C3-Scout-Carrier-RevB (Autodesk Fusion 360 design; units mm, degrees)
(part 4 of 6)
sketch "Molded package profile" plane through (0, 0, 0.2) normal (0, 0, 1) x axis (1, 0, 0)
  line L1 (1.95, -2.45) -> (-1.95, -2.45)
  line L2 (1.95, 2.45) -> (1.95, -2.45)
  line L3 (-1.95, 2.45) -> (1.95, 2.45)
  line L4 (-1.95, -2.45) -> (-1.95, 2.45)
extrude "Extrude1" new body sketch "Molded package profile" along normal blind 1.1
sketch "Lead solder feet profiles" plane through (0, 0, 0) normal (0, 0, 1) x axis (1, 0, 0)
  line L1 (-2.7, 1.665) -> (-3.55, 1.665)
  line L2 (-2.7, 2.145) -> (-2.7, 1.665)
  line L3 (-3.55, 2.145) -> (-2.7, 2.145)
  line L4 (-3.55, 1.665) -> (-3.55, 2.145)
  line L5 (3.55, 1.665) -> (2.7, 1.665)
  line L6 (3.55, 2.145) -> (3.55, 1.665)
  line L7 (2.7, 2.145) -> (3.55, 2.145)
  line L8 (2.7, 1.665) -> (2.7, 2.145)
  line L9 (-2.7, 0.395) -> (-3.55, 0.395)
  line L10 (-2.7, 0.875) -> (-2.7, 0.395)
  line L11 (-3.55, 0.875) -> (-2.7, 0.875)
  line L12 (-3.55, 0.395) -> (-3.55, 0.875)
  line L13 (3.55, 0.395) -> (2.7, 0.395)
  line L14 (3.55, 0.875) -> (3.55, 0.395)
  line L15 (2.7, 0.875) -> (3.55, 0.875)
  line L16 (2.7, 0.395) -> (2.7, 0.875)
  line L17 (-2.7, -0.875) -> (-3.55, -0.875)
  line L18 (-2.7, -0.395) -> (-2.7, -0.875)
  line L19 (-3.55, -0.395) -> (-2.7, -0.395)
  line L20 (-3.55, -0.875) -> (-3.55, -0.395)
  line L21 (3.55, -0.875) -> (2.7, -0.875)
  line L22 (3.55, -0.395) -> (3.55, -0.875)
  line L23 (2.7, -0.395) -> (3.55, -0.395)
  line L24 (2.7, -0.875) -> (2.7, -0.395)
  line L25 (-2.7, -2.145) -> (-3.55, -2.145)
  line L26 (-2.7, -1.665) -> (-2.7, -2.145)
  line L27 (-3.55, -1.665) -> (-2.7, -1.665)
  line L28 (-3.55, -2.145) -> (-3.55, -1.665)
  line L29 (3.55, -2.145) -> (2.7, -2.145)
  line L30 (3.55, -1.665) -> (3.55, -2.145)
  line L31 (2.7, -1.665) -> (3.55, -1.665)
  line L32 (2.7, -2.145) -> (2.7, -1.665)
extrude "Extrude2" new body sketch "Lead solder feet profiles" along normal blind 0.15
work_plane "WorkPlane2" AlongDistance 0.1 ExtraOffset 0
sketch "Formed lead risers profiles" plane through (0, 0, 0.1) normal (0, 0, 1) x axis (1, 0, 0)
  line L1 (-2.12, 1.665) -> (-2.78, 1.665)
  line L2 (-2.12, 2.145) -> (-2.12, 1.665)
  line L3 (-2.78, 2.145) -> (-2.12, 2.145)
  line L4 (-2.78, 1.665) -> (-2.78, 2.145)
  line L5 (2.78, 1.665) -> (2.12, 1.665)
  line L6 (2.78, 2.145) -> (2.78, 1.665)
  line L7 (2.12, 2.145) -> (2.78, 2.145)
  line L8 (2.12, 1.665) -> (2.12, 2.145)
  line L9 (-2.12, 0.395) -> (-2.78, 0.395)
  line L10 (-2.12, 0.875) -> (-2.12, 0.395)
  line L11 (-2.78, 0.875) -> (-2.12, 0.875)
  line L12 (-2.78, 0.395) -> (-2.78, 0.875)
  line L13 (2.78, 0.395) -> (2.12, 0.395)
  line L14 (2.78, 0.875) -> (2.78, 0.395)
  line L15 (2.12, 0.875) -> (2.78, 0.875)
  line L16 (2.12, 0.395) -> (2.12, 0.875)
  line L17 (-2.12, -0.875) -> (-2.78, -0.875)
  line L18 (-2.12, -0.395) -> (-2.12, -0.875)
  line L19 (-2.78, -0.395) -> (-2.12, -0.395)
  line L20 (-2.78, -0.875) -> (-2.78, -0.395)
  line L21 (2.78, -0.875) -> (2.12, -0.875)
  line L22 (2.78, -0.395) -> (2.78, -0.875)
  line L23 (2.12, -0.395) -> (2.78, -0.395)
  line L24 (2.12, -0.875) -> (2.12, -0.395)
  line L25 (-2.12, -2.145) -> (-2.78, -2.145)
  line L26 (-2.12, -1.665) -> (-2.12, -2.145)
  line L27 (-2.78, -1.665) -> (-2.12, -1.665)
  line L28 (-2.78, -2.145) -> (-2.78, -1.665)
  line L29 (2.78, -2.145) -> (2.12, -2.145)
  line L30 (2.78, -1.665) -> (2.78, -2.145)
  line L31 (2.12, -1.665) -> (2.78, -1.665)
  line L32 (2.12, -2.145) -> (2.12, -1.665)
extrude "Extrude3" new body sketch "Formed lead risers profiles" along normal blind 0.45
work_plane "WorkPlane3" AlongDistance 0.45 ExtraOffset 0
sketch "Lead shoulders profiles" plane through (0, 0, 0.45) normal (0, 0, 1) x axis (1, 0, 0)
  line L1 (-1.95, 1.665) -> (-2.2, 1.665)
  line L2 (-1.95, 2.145) -> (-1.95, 1.665)
  line L3 (-2.2, 2.145) -> (-1.95, 2.145)
  line L4 (-2.2, 1.665) -> (-2.2, 2.145)
  line L5 (2.2, 1.665) -> (1.95, 1.665)
  line L6 (2.2, 2.145) -> (2.2, 1.665)
  line L7 (1.95, 2.145) -> (2.2, 2.145)
  line L8 (1.95, 1.665) -> (1.95, 2.145)
  line L9 (-1.95, 0.395) -> (-2.2, 0.395)
  line L10 (-1.95, 0.875) -> (-1.95, 0.395)
  line L11 (-2.2, 0.875) -> (-1.95, 0.875)
  line L12 (-2.2, 0.395) -> (-2.2, 0.875)
  line L13 (2.2, 0.395) -> (1.95, 0.395)
  line L14 (2.2, 0.875) -> (2.2, 0.395)
  line L15 (1.95, 0.875) -> (2.2, 0.875)
  line L16 (1.95, 0.395) -> (1.95, 0.875)
  line L17 (-1.95, -0.875) -> (-2.2, -0.875)
  line L18 (-1.95, -0.395) -> (-1.95, -0.875)
  line L19 (-2.2, -0.395) -> (-1.95, -0.395)
  line L20 (-2.2, -0.875) -> (-2.2, -0.395)
  line L21 (2.2, -0.875) -> (1.95, -0.875)
  line L22 (2.2, -0.395) -> (2.2, -0.875)
  line L23 (1.95, -0.395) -> (2.2, -0.395)
  line L24 (1.95, -0.875) -> (1.95, -0.395)
  line L25 (-1.95, -2.145) -> (-2.2, -2.145)
  line L26 (-1.95, -1.665) -> (-1.95, -2.145)
  line L27 (-2.2, -1.665) -> (-1.95, -1.665)
  line L28 (-2.2, -2.145) -> (-2.2, -1.665)
  line L29 (2.2, -2.145) -> (1.95, -2.145)
  line L30 (2.2, -1.665) -> (2.2, -2.145)
  line L31 (1.95, -1.665) -> (2.2, -1.665)
  line L32 (1.95, -2.145) -> (1.95, -1.665)
extrude "Extrude4" new body sketch "Lead shoulders profiles" along normal blind 0.15
work_plane "WorkPlane4" AlongDistance 1.3 ExtraOffset 0
sketch "Pin 1 indicator profile" plane through (0, 0, 1.3) normal (0, 0, 1) x axis (1, 0, 0)
  circle C1 centre (-1.4, 1.9) radius 0.18
extrude "Extrude5" new body sketch "Pin 1 indicator profile" along normal blind 0.015
work_plane "WorkPlane5" AlongDistance 1.3 ExtraOffset 0
sketch "4056 marking" plane through (0, 0, 1.3) normal (0, 0, 1) x axis (1, 0, 0)
  dimension "d962" = 0.7
  dimension "d963" = "'4056'"
extrude "Extrude6" new body sketch "4056 marking" along normal blind 0.012
work_plane "WorkPlane1" AlongDistance 0.2 ExtraOffset 0
sketch "Molded package profile" plane through (0, 0, 0.2) normal (0, 0, 1) x axis (1, 0, 0)
  line L1 (0.8, -1.45) -> (-0.8, -1.45)
  line L2 (0.8, 1.45) -> (0.8, -1.45)
  line L3 (-0.8, 1.45) -> (0.8, 1.45)
  line L4 (-0.8, -1.45) -> (-0.8, 1.45)
extrude "Extrude1" new body sketch "Molded package profile" along normal blind 0.9
sketch "Lead solder feet profiles" plane through (0, 0, 0) normal (0, 0, 1) x axis (1, 0, 0)
  line L1 (-1.15, 0.71) -> (-1.675, 0.71)
  line L2 (-1.15, 1.19) -> (-1.15, 0.71)
  line L3 (-1.675, 1.19) -> (-1.15, 1.19)
  line L4 (-1.675, 0.71) -> (-1.675, 1.19)
  line L5 (1.675, 0.71) -> (1.15, 0.71)
  line L6 (1.675, 1.19) -> (1.675, 0.71)
  line L7 (1.15, 1.19) -> (1.675, 1.19)
  line L8 (1.15, 0.71) -> (1.15, 1.19)
  line L9 (-1.15, -0.24) -> (-1.675, -0.24)
  line L10 (-1.15, 0.24) -> (-1.15, -0.24)
  line L11 (-1.675, 0.24) -> (-1.15, 0.24)
  line L12 (-1.675, -0.24) -> (-1.675, 0.24)
  line L13 (1.675, -0.24) -> (1.15, -0.24)
  line L14 (1.675, 0.24) -> (1.675, -0.24)
  line L15 (1.15, 0.24) -> (1.675, 0.24)
  line L16 (1.15, -0.24) -> (1.15, 0.24)
  line L17 (-1.15, -1.19) -> (-1.675, -1.19)
  line L18 (-1.15, -0.71) -> (-1.15, -1.19)
  line L19 (-1.675, -0.71) -> (-1.15, -0.71)
  line L20 (-1.675, -1.19) -> (-1.675, -0.71)
  line L21 (1.675, -1.19) -> (1.15, -1.19)
  line L22 (1.675, -0.71) -> (1.675, -1.19)
  line L23 (1.15, -0.71) -> (1.675, -0.71)
  line L24 (1.15, -1.19) -> (1.15, -0.71)
extrude "Extrude2" new body sketch "Lead solder feet profiles" along normal blind 0.15
work_plane "WorkPlane2" AlongDistance 0.1 ExtraOffset 0
sketch "Formed lead risers profiles" plane through (0, 0, 0.1) normal (0, 0, 1) x axis (1, 0, 0)
  line L1 (-0.97, 0.71) -> (-1.23, 0.71)
  line L2 (-0.97, 1.19) -> (-0.97, 0.71)
  line L3 (-1.23, 1.19) -> (-0.97, 1.19)
  line L4 (-1.23, 0.71) -> (-1.23, 1.19)
  line L5 (1.23, 0.71) -> (0.97, 0.71)
  line L6 (1.23, 1.19) -> (1.23, 0.71)
  line L7 (0.97, 1.19) -> (1.23, 1.19)
  line L8 (0.97, 0.71) -> (0.97, 1.19)
  line L9 (-0.97, -0.24) -> (-1.23, -0.24)
  line L10 (-0.97, 0.24) -> (-0.97, -0.24)
  line L11 (-1.23, 0.24) -> (-0.97, 0.24)
  line L12 (-1.23, -0.24) -> (-1.23, 0.24)
  line L13 (1.23, -0.24) -> (0.97, -0.24)
  line L14 (1.23, 0.24) -> (1.23, -0.24)
  line L15 (0.97, 0.24) -> (1.23, 0.24)
  line L16 (0.97, -0.24) -> (0.97, 0.24)
  line L17 (-0.97, -1.19) -> (-1.23, -1.19)
  line L18 (-0.97, -0.71) -> (-0.97, -1.19)
  line L19 (-1.23, -0.71) -> (-0.97, -0.71)
  line L20 (-1.23, -1.19) -> (-1.23, -0.71)
  line L21 (1.23, -1.19) -> (0.97, -1.19)
  line L22 (1.23, -0.71) -> (1.23, -1.19)
  line L23 (0.97, -0.71) -> (1.23, -0.71)
  line L24 (0.97, -1.19) -> (0.97, -0.71)
extrude "Extrude3" new body sketch "Formed lead risers profiles" along normal blind 0.45
work_plane "WorkPlane3" AlongDistance 0.45 ExtraOffset 0
sketch "Lead shoulders profiles" plane through (0, 0, 0.45) normal (0, 0, 1) x axis (1, 0, 0)
  line L1 (-0.8, 0.71) -> (-1.05, 0.71)
  line L2 (-0.8, 1.19) -> (-0.8, 0.71)
  line L3 (-1.05, 1.19) -> (-0.8, 1.19)
  line L4 (-1.05, 0.71) -> (-1.05, 1.19)
  line L5 (1.05, 0.71) -> (0.8, 0.71)
  line L6 (1.05, 1.19) -> (1.05, 0.71)
  line L7 (0.8, 1.19) -> (1.05, 1.19)
  line L8 (0.8, 0.71) -> (0.8, 1.19)
  line L9 (-0.8, -0.24) -> (-1.05, -0.24)
  line L10 (-0.8, 0.24) -> (-0.8, -0.24)
  line L11 (-1.05, 0.24) -> (-0.8, 0.24)
  line L12 (-1.05, -0.24) -> (-1.05, 0.24)
  line L13 (1.05, -0.24) -> (0.8, -0.24)
  line L14 (1.05, 0.24) -> (1.05, -0.24)
  line L15 (0.8, 0.24) -> (1.05, 0.24)
  line L16 (0.8, -0.24) -> (0.8, 0.24)
  line L17 (-0.8, -1.19) -> (-1.05, -1.19)
  line L18 (-0.8, -0.71) -> (-0.8, -1.19)
  line L19 (-1.05, -0.71) -> (-0.8, -0.71)
  line L20 (-1.05, -1.19) -> (-1.05, -0.71)
  line L21 (1.05, -1.19) -> (0.8, -1.19)
  line L22 (1.05, -0.71) -> (1.05, -1.19)
  line L23 (0.8, -0.71) -> (1.05, -0.71)
  line L24 (0.8, -1.19) -> (0.8, -0.71)
extrude "Extrude4" new body sketch "Lead shoulders profiles" along normal blind 0.15
work_plane "WorkPlane4" AlongDistance 1.1 ExtraOffset 0
sketch "Pin 1 indicator profile" plane through (0, 0, 1.1) normal (0, 0, 1) x axis (1, 0, 0)
  circle C1 centre (-0.25, 0.9) radius 0.18
extrude "Extrude5" new body sketch "Pin 1 indicator profile" along normal blind 0.015
work_plane "WorkPlane1" AlongDistance 0.2 ExtraOffset 0
sketch "Molded package profile" plane through (0, 0, 0.2) normal (0, 0, 1) x axis (1, 0, 0)
  line L1 (2.2, -1.465) -> (-2.2, -1.465)
  line L2 (2.2, 1.465) -> (2.2, -1.465)
  line L3 (-2.2, 1.465) -> (2.2, 1.465)
  line L4 (-2.2, -1.465) -> (-2.2, 1.465)
extrude "Extrude1" new body sketch "Molded package profile" along normal blind 0.9
sketch "Lead solder feet profiles" plane through (0, 0, 0) normal (0, 0, 1) x axis (1, 0, 0)
  line L1 (-2.9, 0.815) -> (-3.65, 0.815)
  line L2 (-2.9, 1.135) -> (-2.9, 0.815)
  line L3 (-3.65, 1.135) -> (-2.9, 1.135)
  line L4 (-3.65, 0.815) -> (-3.65, 1.135)
  line L5 (3.65, 0.815) -> (2.9, 0.815)
  line L6 (3.65, 1.135) -> (3.65, 0.815)
  line L7 (2.9, 1.135) -> (3.65, 1.135)
  line L8 (2.9, 0.815) -> (2.9, 1.135)
  line L9 (-2.9, 0.165) -> (-3.65, 0.165)
  line L10 (-2.9, 0.485) -> (-2.9, 0.165)
  line L11 (-3.65, 0.485) -> (-2.9, 0.485)
  line L12 (-3.65, 0.165) -> (-3.65, 0.485)
  line L13 (3.65, 0.165) -> (2.9, 0.165)
  line L14 (3.65, 0.485) -> (3.65, 0.165)
  line L15 (2.9, 0.485) -> (3.65, 0.485)
  line L16 (2.9, 0.165) -> (2.9, 0.485)
  line L17 (-2.9, -0.485) -> (-3.65, -0.485)
  line L18 (-2.9, -0.165) -> (-2.9, -0.485)
  line L19 (-3.65, -0.165) -> (-2.9, -0.165)
  line L20 (-3.65, -0.485) -> (-3.65, -0.165)
  line L21 (3.65, -0.485) -> (2.9, -0.485)
  line L22 (3.65, -0.165) -> (3.65, -0.485)
  line L23 (2.9, -0.165) -> (3.65, -0.165)
  line L24 (2.9, -0.485) -> (2.9, -0.165)
  line L25 (-2.9, -1.135) -> (-3.65, -1.135)
  line L26 (-2.9, -0.815) -> (-2.9, -1.135)
  line L27 (-3.65, -0.815) -> (-2.9, -0.815)
  line L28 (-3.65, -1.135) -> (-3.65, -0.815)
  line L29 (3.65, -1.135) -> (2.9, -1.135)
  line L30 (3.65, -0.815) -> (3.65, -1.135)
  line L31 (2.9, -0.815) -> (3.65, -0.815)
  line L32 (2.9, -1.135) -> (2.9, -0.815)
extrude "Extrude2" new body sketch "Lead solder feet profiles" along normal blind 0.15
work_plane "WorkPlane2" AlongDistance 0.1 ExtraOffset 0
sketch "Formed lead risers profiles" plane through (0, 0, 0.1) normal (0, 0, 1) x axis (1, 0, 0)
  line L1 (-2.37, 0.815) -> (-2.98, 0.815)
  line L2 (-2.37, 1.135) -> (-2.37, 0.815)
  line L3 (-2.98, 1.135) -> (-2.37, 1.135)
  line L4 (-2.98, 0.815) -> (-2.98, 1.135)
  line L5 (2.98, 0.815) -> (2.37, 0.815)
  line L6 (2.98, 1.135) -> (2.98, 0.815)
  line L7 (2.37, 1.135) -> (2.98, 1.135)
  line L8 (2.37, 0.815) -> (2.37, 1.135)
  line L9 (-2.37, 0.165) -> (-2.98, 0.165)
  line L10 (-2.37, 0.485) -> (-2.37, 0.165)
  line L11 (-2.98, 0.485) -> (-2.37, 0.485)
  line L12 (-2.98, 0.165) -> (-2.98, 0.485)
  line L13 (2.98, 0.165) -> (2.37, 0.165)
  line L14 (2.98, 0.485) -> (2.98, 0.165)
  line L15 (2.37, 0.485) -> (2.98, 0.485)
  line L16 (2.37, 0.165) -> (2.37, 0.485)
  line L17 (-2.37, -0.485) -> (-2.98, -0.485)
  line L18 (-2.37, -0.165) -> (-2.37, -0.485)
  line L19 (-2.98, -0.165) -> (-2.37, -0.165)
  line L20 (-2.98, -0.485) -> (-2.98, -0.165)
  line L21 (2.98, -0.485) -> (2.37, -0.485)
  line L22 (2.98, -0.165) -> (2.98, -0.485)
  line L23 (2.37, -0.165) -> (2.98, -0.165)
  line L24 (2.37, -0.485) -> (2.37, -0.165)
  line L25 (-2.37, -1.135) -> (-2.98, -1.135)
  line L26 (-2.37, -0.815) -> (-2.37, -1.135)
  line L27 (-2.98, -0.815) -> (-2.37, -0.815)
  line L28 (-2.98, -1.135) -> (-2.98, -0.815)
  line L29 (2.98, -1.135) -> (2.37, -1.135)
  line L30 (2.98, -0.815) -> (2.98, -1.135)
  line L31 (2.37, -0.815) -> (2.98, -0.815)
  line L32 (2.37, -1.135) -> (2.37, -0.815)
extrude "Extrude3" new body sketch "Formed lead risers profiles" along normal blind 0.45
work_plane "WorkPlane3" AlongDistance 0.45 ExtraOffset 0
sketch "Lead shoulders profiles" plane through (0, 0, 0.45) normal (0, 0, 1) x axis (1, 0, 0)
  line L1 (-2.2, 0.815) -> (-2.45, 0.815)
  line L2 (-2.2, 1.135) -> (-2.2, 0.815)
  line L3 (-2.45, 1.135) -> (-2.2, 1.135)
  line L4 (-2.45, 0.815) -> (-2.45, 1.135)
  line L5 (2.45, 0.815) -> (2.2, 0.815)
  line L6 (2.45, 1.135) -> (2.45, 0.815)
  line L7 (2.2, 1.135) -> (2.45, 1.135)
  line L8 (2.2, 0.815) -> (2.2, 1.135)
  line L9 (-2.2, 0.165) -> (-2.45, 0.165)
  line L10 (-2.2, 0.485) -> (-2.2, 0.165)
  line L11 (-2.45, 0.485) -> (-2.2, 0.485)
  line L12 (-2.45, 0.165) -> (-2.45, 0.485)
  line L13 (2.45, 0.165) -> (2.2, 0.165)
  line L14 (2.45, 0.485) -> (2.45, 0.165)
  line L15 (2.2, 0.485) -> (2.45, 0.485)
  line L16 (2.2, 0.165) -> (2.2, 0.485)
  line L17 (-2.2, -0.485) -> (-2.45, -0.485)
  line L18 (-2.2, -0.165) -> (-2.2, -0.485)
  line L19 (-2.45, -0.165) -> (-2.2, -0.165)
  line L20 (-2.45, -0.485) -> (-2.45, -0.165)
  line L21 (2.45, -0.485) -> (2.2, -0.485)
  line L22 (2.45, -0.165) -> (2.45, -0.485)
  line L23 (2.2, -0.165) -> (2.45, -0.165)
  line L24 (2.2, -0.485) -> (2.2, -0.165)
  line L25 (-2.2, -1.135) -> (-2.45, -1.135)
  line L26 (-2.2, -0.815) -> (-2.2, -1.135)
  line L27 (-2.45, -0.815) -> (-2.2, -0.815)
  line L28 (-2.45, -1.135) -> (-2.45, -0.815)
  line L29 (2.45, -1.135) -> (2.2, -1.135)
  line L30 (2.45, -0.815) -> (2.45, -1.135)
  line L31 (2.2, -0.815) -> (2.45, -0.815)
  line L32 (2.2, -1.135) -> (2.2, -0.815)
extrude "Extrude4" new body sketch "Lead shoulders profiles" along normal blind 0.15
work_plane "WorkPlane4" AlongDistance 1.1 ExtraOffset 0
sketch "Pin 1 indicator profile" plane through (0, 0, 1.1) normal (0, 0, 1) x axis (1, 0, 0)
  circle C1 centre (-1.65, 0.915) radius 0.18
extrude "Extrude5" new body sketch "Pin 1 indicator profile" along normal blind 0.015
work_plane "WorkPlane1" AlongDistance 0.2 ExtraOffset 0
sketch "Molded package profile" plane through (0, 0, 0.2) normal (0, 0, 1) x axis (1, 0, 0)
  line L1 (0.8, -1.45) -> (-0.8, -1.45)
  line L2 (0.8, 1.45) -> (0.8, -1.45)
  line L3 (-0.8, 1.45) -> (0.8, 1.45)
  line L4 (-0.8, -1.45) -> (-0.8, 1.45)
extrude "Extrude1" new body sketch "Molded package profile" along normal blind 0.9
sketch "Lead solder feet profiles" plane through (0, 0, 0) normal (0, 0, 1) x axis (1, 0, 0)
  line L1 (-1.15, 0.71) -> (-1.675, 0.71)
  line L2 (-1.15, 1.19) -> (-1.15, 0.71)
  line L3 (-1.675, 1.19) -> (-1.15, 1.19)
  line L4 (-1.675, 0.71) -> (-1.675, 1.19)
  line L5 (1.675, 0.71) -> (1.15, 0.71)
  line L6 (1.675, 1.19) -> (1.675, 0.71)
  line L7 (1.15, 1.19) -> (1.675, 1.19)
  line L8 (1.15, 0.71) -> (1.15, 1.19)
  line L9 (-1.15, -0.24) -> (-1.675, -0.24)
  line L10 (-1.15, 0.24) -> (-1.15, -0.24)
  line L11 (-1.675, 0.24) -> (-1.15, 0.24)
  line L12 (-1.675, -0.24) -> (-1.675, 0.24)
  line L13 (1.675, -0.24) -> (1.15, -0.24)
  line L14 (1.675, 0.24) -> (1.675, -0.24)
  line L15 (1.15, 0.24) -> (1.675, 0.24)
  line L16 (1.15, -0.24) -> (1.15, 0.24)
  line L17 (-1.15, -1.19) -> (-1.675, -1.19)
  line L18 (-1.15, -0.71) -> (-1.15, -1.19)
  line L19 (-1.675, -0.71) -> (-1.15, -0.71)
  line L20 (-1.675, -1.19) -> (-1.675, -0.71)
  line L21 (1.675, -1.19) -> (1.15, -1.19)
  line L22 (1.675, -0.71) -> (1.675, -1.19)
  line L23 (1.15, -0.71) -> (1.675, -0.71)
  line L24 (1.15, -1.19) -> (1.15, -0.71)
extrude "Extrude2" new body sketch "Lead solder feet profiles" along normal blind 0.15
work_plane "WorkPlane2" AlongDistance 0.1 ExtraOffset 0
sketch "Formed lead risers profiles" plane through (0, 0, 0.1) normal (0, 0, 1) x axis (1, 0, 0)
  line L1 (-0.97, 0.71) -> (-1.23, 0.71)
  line L2 (-0.97, 1.19) -> (-0.97, 0.71)
  line L3 (-1.23, 1.19) -> (-0.97, 1.19)
  line L4 (-1.23, 0.71) -> (-1.23, 1.19)
  line L5 (1.23, 0.71) -> (0.97, 0.71)
  line L6 (1.23, 1.19) -> (1.23, 0.71)
  line L7 (0.97, 1.19) -> (1.23, 1.19)
  line L8 (0.97, 0.71) -> (0.97, 1.19)
  line L9 (-0.97, -0.24) -> (-1.23, -0.24)
  line L10 (-0.97, 0.24) -> (-0.97, -0.24)
  line L11 (-1.23, 0.24) -> (-0.97, 0.24)
  line L12 (-1.23, -0.24) -> (-1.23, 0.24)
  line L13 (1.23, -0.24) -> (0.97, -0.24)
  line L14 (1.23, 0.24) -> (1.23, -0.24)
  line L15 (0.97, 0.24) -> (1.23, 0.24)
  line L16 (0.97, -0.24) -> (0.97, 0.24)
  line L17 (-0.97, -1.19) -> (-1.23, -1.19)
  line L18 (-0.97, -0.71) -> (-0.97, -1.19)
  line L19 (-1.23, -0.71) -> (-0.97, -0.71)
  line L20 (-1.23, -1.19) -> (-1.23, -0.71)
  line L21 (1.23, -1.19) -> (0.97, -1.19)
  line L22 (1.23, -0.71) -> (1.23, -1.19)
  line L23 (0.97, -0.71) -> (1.23, -0.71)
  line L24 (0.97, -1.19) -> (0.97, -0.71)
extrude "Extrude3" new body sketch "Formed lead risers profiles" along normal blind 0.45
work_plane "WorkPlane3" AlongDistance 0.45 ExtraOffset 0
sketch "Lead shoulders profiles" plane through (0, 0, 0.45) normal (0, 0, 1) x axis (1, 0, 0)
  line L1 (-0.8, 0.71) -> (-1.05, 0.71)
  line L2 (-0.8, 1.19) -> (-0.8, 0.71)
  line L3 (-1.05, 1.19) -> (-0.8, 1.19)
  line L4 (-1.05, 0.71) -> (-1.05, 1.19)
  line L5 (1.05, 0.71) -> (0.8, 0.71)
  line L6 (1.05, 1.19) -> (1.05, 0.71)
  line L7 (0.8, 1.19) -> (1.05, 1.19)
  line L8 (0.8, 0.71) -> (0.8, 1.19)
  line L9 (-0.8, -0.24) -> (-1.05, -0.24)
  line L10 (-0.8, 0.24) -> (-0.8, -0.24)
  line L11 (-1.05, 0.24) -> (-0.8, 0.24)
  line L12 (-1.05, -0.24) -> (-1.05, 0.24)
  line L13 (1.05, -0.24) -> (0.8, -0.24)
  line L14 (1.05, 0.24) -> (1.05, -0.24)
  line L15 (0.8, 0.24) -> (1.05, 0.24)
  line L16 (0.8, -0.24) -> (0.8, 0.24)
  line L17 (-0.8, -1.19) -> (-1.05, -1.19)
  line L18 (-0.8, -0.71) -> (-0.8, -1.19)
  line L19 (-1.05, -0.71) -> (-0.8, -0.71)
  line L20 (-1.05, -1.19) -> (-1.05, -0.71)
  line L21 (1.05, -1.19) -> (0.8, -1.19)
  line L22 (1.05, -0.71) -> (1.05, -1.19)
  line L23 (0.8, -0.71) -> (1.05, -0.71)
  line L24 (0.8, -1.19) -> (0.8, -0.71)
extrude "Extrude4" new body sketch "Lead shoulders profiles" along normal blind 0.15
work_plane "WorkPlane4" AlongDistance 1.1 ExtraOffset 0
sketch "Pin 1 indicator profile" plane through (0, 0, 1.1) normal (0, 0, 1) x axis (1, 0, 0)
  circle C1 centre (-0.25, 0.9) radius 0.18
extrude "Extrude5" new body sketch "Pin 1 indicator profile" along normal blind 0.015
work_plane "WorkPlane1" AlongDistance 0.2 ExtraOffset 0
sketch "Molded package profile" plane through (0, 0, 0.2) normal (0, 0, 1) x axis (1, 0, 0)
  line L1 (2.2, -2.5) -> (-2.2, -2.5)
  line L2 (2.2, 2.5) -> (2.2, -2.5)
  line L3 (-2.2, 2.5) -> (2.2, 2.5)
  line L4 (-2.2, -2.5) -> (-2.2, 2.5)
extrude "Extrude1" new body sketch "Molded package profile" along normal blind 0.9
sketch "Lead solder feet profiles" plane through (0, 0, 0) normal (0, 0, 1) x axis (1, 0, 0)
  line L1 (-2.9, 1.79) -> (-3.65, 1.79)
  line L2 (-2.9, 2.11) -> (-2.9, 1.79)
  line L3 (-3.65, 2.11) -> (-2.9, 2.11)
  line L4 (-3.65, 1.79) -> (-3.65, 2.11)
  line L5 (3.65, 1.79) -> (2.9, 1.79)
  line L6 (3.65, 2.11) -> (3.65, 1.79)
  line L7 (2.9, 2.11) -> (3.65, 2.11)
  line L8 (2.9, 1.79) -> (2.9, 2.11)
  line L9 (-2.9, 1.14) -> (-3.65, 1.14)
  line L10 (-2.9, 1.46) -> (-2.9, 1.14)
  line L11 (-3.65, 1.46) -> (-2.9, 1.46)
  line L12 (-3.65, 1.14) -> (-3.65, 1.46)
  line L13 (3.65, 1.14) -> (2.9, 1.14)
  line L14 (3.65, 1.46) -> (3.65, 1.14)
  line L15 (2.9, 1.46) -> (3.65, 1.46)
  line L16 (2.9, 1.14) -> (2.9, 1.46)
  line L17 (-2.9, 0.49) -> (-3.65, 0.49)
  line L18 (-2.9, 0.81) -> (-2.9, 0.49)
  line L19 (-3.65, 0.81) -> (-2.9, 0.81)
  line L20 (-3.65, 0.49) -> (-3.65, 0.81)
  line L21 (3.65, 0.49) -> (2.9, 0.49)
  line L22 (3.65, 0.81) -> (3.65, 0.49)
  line L23 (2.9, 0.81) -> (3.65, 0.81)
  line L24 (2.9, 0.49) -> (2.9, 0.81)
  line L25 (-2.9, -0.16) -> (-3.65, -0.16)
  line L26 (-2.9, 0.16) -> (-2.9, -0.16)
  line L27 (-3.65, 0.16) -> (-2.9, 0.16)
  line L28 (-3.65, -0.16) -> (-3.65, 0.16)
  line L29 (3.65, -0.16) -> (2.9, -0.16)
  line L30 (3.65, 0.16) -> (3.65, -0.16)
  line L31 (2.9, 0.16) -> (3.65, 0.16)
  line L32 (2.9, -0.16) -> (2.9, 0.16)
  line L33 (-2.9, -0.81) -> (-3.65, -0.81)
  line L34 (-2.9, -0.49) -> (-2.9, -0.81)
  line L35 (-3.65, -0.49) -> (-2.9, -0.49)
  line L36 (-3.65, -0.81) -> (-3.65, -0.49)
  line L37 (3.65, -0.81) -> (2.9, -0.81)
  line L38 (3.65, -0.49) -> (3.65, -0.81)
  line L39 (2.9, -0.49) -> (3.65, -0.49)
  line L40 (2.9, -0.81) -> (2.9, -0.49)
  line L41 (-2.9, -1.46) -> (-3.65, -1.46)
  line L42 (-2.9, -1.14) -> (-2.9, -1.46)
  line L43 (-3.65, -1.14) -> (-2.9, -1.14)
  line L44 (-3.65, -1.46) -> (-3.65, -1.14)
  line L45 (3.65, -1.46) -> (2.9, -1.46)
  line L46 (3.65, -1.14) -> (3.65, -1.46)
  line L47 (2.9, -1.14) -> (3.65, -1.14)
  line L48 (2.9, -1.46) -> (2.9, -1.14)
  line L49 (-2.9, -2.11) -> (-3.65, -2.11)
  line L50 (-2.9, -1.79) -> (-2.9, -2.11)
  line L51 (-3.65, -1.79) -> (-2.9, -1.79)
  line L52 (-3.65, -2.11) -> (-3.65, -1.79)
  line L53 (3.65, -2.11) -> (2.9, -2.11)
  line L54 (3.65, -1.79) -> (3.65, -2.11)
  line L55 (2.9, -1.79) -> (3.65, -1.79)
  line L56 (2.9, -2.11) -> (2.9, -1.79)
extrude "Extrude2" new body sketch "Lead solder feet profiles" along normal blind 0.15
work_plane "WorkPlane2" AlongDistance 0.1 ExtraOffset 0
sketch "Formed lead risers profiles" plane through (0, 0, 0.1) normal (0, 0, 1) x axis (1, 0, 0)
  line L1 (-2.37, 1.79) -> (-2.98, 1.79)
  line L2 (-2.37, 2.11) -> (-2.37, 1.79)
  line L3 (-2.98, 2.11) -> (-2.37, 2.11)
  line L4 (-2.98, 1.79) -> (-2.98, 2.11)
  line L5 (2.98, 1.79) -> (2.37, 1.79)
  line L6 (2.98, 2.11) -> (2.98, 1.79)
  line L7 (2.37, 2.11) -> (2.98, 2.11)
  line L8 (2.37, 1.79) -> (2.37, 2.11)
  line L9 (-2.37, 1.14) -> (-2.98, 1.14)
  line L10 (-2.37, 1.46) -> (-2.37, 1.14)
  line L11 (-2.98, 1.46) -> (-2.37, 1.46)
  line L12 (-2.98, 1.14) -> (-2.98, 1.46)
  line L13 (2.98, 1.14) -> (2.37, 1.14)
  line L14 (2.98, 1.46) -> (2.98, 1.14)
  line L15 (2.37, 1.46) -> (2.98, 1.46)
  line L16 (2.37, 1.14) -> (2.37, 1.46)
  line L17 (-2.37, 0.49) -> (-2.98, 0.49)
  line L18 (-2.37, 0.81) -> (-2.37, 0.49)
  line L19 (-2.98, 0.81) -> (-2.37, 0.81)
  line L20 (-2.98, 0.49) -> (-2.98, 0.81)
  line L21 (2.98, 0.49) -> (2.37, 0.49)
  line L22 (2.98, 0.81) -> (2.98, 0.49)
  line L23 (2.37, 0.81) -> (2.98, 0.81)
  line L24 (2.37, 0.49) -> (2.37, 0.81)
  line L25 (-2.37, -0.16) -> (-2.98, -0.16)
  line L26 (-2.37, 0.16) -> (-2.37, -0.16)
  line L27 (-2.98, 0.16) -> (-2.37, 0.16)
  line L28 (-2.98, -0.16) -> (-2.98, 0.16)
  line L29 (2.98, -0.16) -> (2.37, -0.16)
  line L30 (2.98, 0.16) -> (2.98, -0.16)
  line L31 (2.37, 0.16) -> (2.98, 0.16)
  line L32 (2.37, -0.16) -> (2.37, 0.16)
  line L33 (-2.37, -0.81) -> (-2.98, -0.81)
  line L34 (-2.37, -0.49) -> (-2.37, -0.81)
  line L35 (-2.98, -0.49) -> (-2.37, -0.49)
  line L36 (-2.98, -0.81) -> (-2.98, -0.49)
  line L37 (2.98, -0.81) -> (2.37, -0.81)
  line L38 (2.98, -0.49) -> (2.98, -0.81)
  line L39 (2.37, -0.49) -> (2.98, -0.49)
  line L40 (2.37, -0.81) -> (2.37, -0.49)
  line L41 (-2.37, -1.46) -> (-2.98, -1.46)
  line L42 (-2.37, -1.14) -> (-2.37, -1.46)
  line L43 (-2.98, -1.14) -> (-2.37, -1.14)
  line L44 (-2.98, -1.46) -> (-2.98, -1.14)
  line L45 (2.98, -1.46) -> (2.37, -1.46)
  line L46 (2.98, -1.14) -> (2.98, -1.46)
  line L47 (2.37, -1.14) -> (2.98, -1.14)
  line L48 (2.37, -1.46) -> (2.37, -1.14)
  line L49 (-2.37, -2.11) -> (-2.98, -2.11)
  line L50 (-2.37, -1.79) -> (-2.37, -2.11)
  line L51 (-2.98, -1.79) -> (-2.37, -1.79)
  line L52 (-2.98, -2.11) -> (-2.98, -1.79)
  line L53 (2.98, -2.11) -> (2.37, -2.11)
  line L54 (2.98, -1.79) -> (2.98, -2.11)
  line L55 (2.37, -1.79) -> (2.98, -1.79)
  line L56 (2.37, -2.11) -> (2.37, -1.79)
extrude "Extrude3" new body sketch "Formed lead risers profiles" along normal blind 0.45
work_plane "WorkPlane3" AlongDistance 0.45 ExtraOffset 0
sketch "Lead shoulders profiles" plane through (0, 0, 0.45) normal (0, 0, 1) x axis (1, 0, 0)
  line L1 (-2.2, 1.79) -> (-2.45, 1.79)
  line L2 (-2.2, 2.11) -> (-2.2, 1.79)
  line L3 (-2.45, 2.11) -> (-2.2, 2.11)
  line L4 (-2.45, 1.79) -> (-2.45, 2.11)
  line L5 (2.45, 1.79) -> (2.2, 1.79)
  line L6 (2.45, 2.11) -> (2.45, 1.79)
  line L7 (2.2, 2.11) -> (2.45, 2.11)
  line L8 (2.2, 1.79) -> (2.2, 2.11)
  line L9 (-2.2, 1.14) -> (-2.45, 1.14)
  line L10 (-2.2, 1.46) -> (-2.2, 1.14)
  line L11 (-2.45, 1.46) -> (-2.2, 1.46)
  line L12 (-2.45, 1.14) -> (-2.45, 1.46)
  line L13 (2.45, 1.14) -> (2.2, 1.14)
  line L14 (2.45, 1.46) -> (2.45, 1.14)
  line L15 (2.2, 1.46) -> (2.45, 1.46)
  line L16 (2.2, 1.14) -> (2.2, 1.46)
  line L17 (-2.2, 0.49) -> (-2.45, 0.49)
  line L18 (-2.2, 0.81) -> (-2.2, 0.49)
  line L19 (-2.45, 0.81) -> (-2.2, 0.81)
  line L20 (-2.45, 0.49) -> (-2.45, 0.81)
  line L21 (2.45, 0.49) -> (2.2, 0.49)
  line L22 (2.45, 0.81) -> (2.45, 0.49)
  line L23 (2.2, 0.81) -> (2.45, 0.81)
  line L24 (2.2, 0.49) -> (2.2, 0.81)
  line L25 (-2.2, -0.16) -> (-2.45, -0.16)
  line L26 (-2.2, 0.16) -> (-2.2, -0.16)
  line L27 (-2.45, 0.16) -> (-2.2, 0.16)
  line L28 (-2.45, -0.16) -> (-2.45, 0.16)
  line L29 (2.45, -0.16) -> (2.2, -0.16)
  line L30 (2.45, 0.16) -> (2.45, -0.16)
  line L31 (2.2, 0.16) -> (2.45, 0.16)
  line L32 (2.2, -0.16) -> (2.2, 0.16)
  line L33 (-2.2, -0.81) -> (-2.45, -0.81)
  line L34 (-2.2, -0.49) -> (-2.2, -0.81)
  line L35 (-2.45, -0.49) -> (-2.2, -0.49)
  line L36 (-2.45, -0.81) -> (-2.45, -0.49)
  line L37 (2.45, -0.81) -> (2.2, -0.81)
  line L38 (2.45, -0.49) -> (2.45, -0.81)
  line L39 (2.2, -0.49) -> (2.45, -0.49)
  line L40 (2.2, -0.81) -> (2.2, -0.49)
  line L41 (-2.2, -1.46) -> (-2.45, -1.46)
  line L42 (-2.2, -1.14) -> (-2.2, -1.46)
  line L43 (-2.45, -1.14) -> (-2.2, -1.14)
  line L44 (-2.45, -1.46) -> (-2.45, -1.14)
  line L45 (2.45, -1.46) -> (2.2, -1.46)
  line L46 (2.45, -1.14) -> (2.45, -1.46)
  line L47 (2.2, -1.14) -> (2.45, -1.14)
  line L48 (2.2, -1.46) -> (2.2, -1.14)
  line L49 (-2.2, -2.11) -> (-2.45, -2.11)
  line L50 (-2.2, -1.79) -> (-2.2, -2.11)
  line L51 (-2.45, -1.79) -> (-2.2, -1.79)
  line L52 (-2.45, -2.11) -> (-2.45, -1.79)
  line L53 (2.45, -2.11) -> (2.2, -2.11)
  line L54 (2.45, -1.79) -> (2.45, -2.11)
  line L55 (2.2, -1.79) -> (2.45, -1.79)
  line L56 (2.2, -2.11) -> (2.2, -1.79)
extrude "Extrude4" new body sketch "Lead shoulders profiles" along normal blind 0.15
work_plane "WorkPlane4" AlongDistance 1.1 ExtraOffset 0
sketch "Pin 1 indicator profile" plane through (0, 0, 1.1) normal (0, 0, 1) x axis (1, 0, 0)
  circle C1 centre (-1.65, 1.95) radius 0.18
extrude "Extrude5" new body sketch "Pin 1 indicator profile" along normal blind 0.015
sketch "USB-C shield profile" plane through (0, 0, 0) normal (0, 0, 1) x axis (1, 0, 0)
  line L1 (4.47, -3.4) -> (-4.47, -3.4)
  line L2 (4.47, 3.4) -> (4.47, -3.4)
  line L3 (-4.47, 3.4) -> (4.47, 3.4)
  line L4 (-4.47, -3.4) -> (-4.47, 3.4)
extrude "Extrude1" new body sketch "USB-C shield profile" along normal blind 3.16
work_plane "WorkPlane1" AlongDistance 0.35 ExtraOffset 0
sketch "Open connector mouth profile" plane through (0, 0, 0.35) normal (0, 0, 1) x axis (1, 0, 0)
  line L1 (3.8, -3.5) -> (-3.8, -3.5)
  line L2 (3.8, 2.3) -> (3.8, -3.5)
  line L3 (-3.8, 2.3) -> (3.8, 2.3)
  line L4 (-3.8, -3.5) -> (-3.8, 2.3)
extrude "Extrude2" cut sketch "Open connector mouth profile" along normal blind 2.5
work_plane "WorkPlane2" AlongDistance 1.3 ExtraOffset 0
sketch "Insulated connector tongue profile" plane through (0, 0, 1.3) normal (0, 0, 1) x axis (1, 0, 0)
  line L1 (3, -3.25) -> (-3, -3.25)
  line L2 (3, 1.9) -> (3, -3.25)
  line L3 (-3, 1.9) -> (3, 1.9)
  line L4 (-3, -3.25) -> (-3, 1.9)
extrude "Extrude3" new body sketch "Insulated connector tongue profile" along normal blind 0.55
work_plane "WorkPlane3" AlongDistance 1.85 ExtraOffset 0
sketch "Mating contacts profiles" plane through (0, 0, 1.85) normal (0, 0, 1) x axis (1, 0, 0)
  line L1 (-2.4, -3) -> (-2.6, -3)
  line L2 (-2.4, 1) -> (-2.4, -3)
  line L3 (-2.6, 1) -> (-2.4, 1)
  line L4 (-2.6, -3) -> (-2.6, 1)
  line L5 (-1.93, -3) -> (-2.13, -3)
  line L6 (-1.93, 1) -> (-1.93, -3)
  line L7 (-2.13, 1) -> (-1.93, 1)
  line L8 (-2.13, -3) -> (-2.13, 1)
  line L9 (-1.46, -3) -> (-1.66, -3)
  line L10 (-1.46, 1) -> (-1.46, -3)
  line L11 (-1.66, 1) -> (-1.46, 1)
  line L12 (-1.66, -3) -> (-1.66, 1)
  line L13 (-0.99, -3) -> (-1.19, -3)
  line L14 (-0.99, 1) -> (-0.99, -3)
  line L15 (-1.19, 1) -> (-0.99, 1)
  line L16 (-1.19, -3) -> (-1.19, 1)
  line L17 (-0.52, -3) -> (-0.72, -3)
  line L18 (-0.52, 1) -> (-0.52, -3)
  line L19 (-0.72, 1) -> (-0.52, 1)
  line L20 (-0.72, -3) -> (-0.72, 1)
  line L21 (-0.05, -3) -> (-0.25, -3)
  line L22 (-0.05, 1) -> (-0.05, -3)
  line L23 (-0.25, 1) -> (-0.05, 1)
  line L24 (-0.25, -3) -> (-0.25, 1)
  line L25 (0.42, -3) -> (0.22, -3)
  line L26 (0.42, 1) -> (0.42, -3)
  line L27 (0.22, 1) -> (0.42, 1)
  line L28 (0.22, -3) -> (0.22, 1)
  line L29 (0.89, -3) -> (0.69, -3)
  line L30 (0.89, 1) -> (0.89, -3)
  line L31 (0.69, 1) -> (0.89, 1)
  line L32 (0.69, -3) -> (0.69, 1)
  line L33 (1.36, -3) -> (1.16, -3)
  line L34 (1.36, 1) -> (1.36, -3)
  line L35 (1.16, 1) -> (1.36, 1)
  line L36 (1.16, -3) -> (1.16, 1)
  line L37 (1.83, -3) -> (1.63, -3)
  line L38 (1.83, 1) -> (1.83, -3)
  line L39 (1.63, 1) -> (1.83, 1)
  line L40 (1.63, -3) -> (1.63, 1)
  line L41 (2.3, -3) -> (2.1, -3)
  line L42 (2.3, 1) -> (2.3, -3)
  line L43 (2.1, 1) -> (2.3, 1)
  line L44 (2.1, -3) -> (2.1, 1)
  line L45 (2.77, -3) -> (2.57, -3)
  line L46 (2.77, 1) -> (2.77, -3)
  line L47 (2.57, 1) -> (2.77, 1)
  line L48 (2.57, -3) -> (2.57, 1)
extrude "Extrude4" new body sketch "Mating contacts profiles" along normal blind 0.025
sketch "Board terminations profiles" plane through (0, 0, 0) normal (0, 0, 1) x axis (1, 0, 0)
  line L1 (-2.35, 2.48) -> (-3.15, 2.48)
  line L2 (-2.35, 3.68) -> (-2.35, 2.48)
  line L3 (-3.15, 3.68) -> (-2.35, 3.68)
  line L4 (-3.15, 2.48) -> (-3.15, 3.68)
  line L5 (-1.14, 2.48) -> (-1.9, 2.48)
  line L6 (-1.14, 3.68) -> (-1.14, 2.48)
  line L7 (-1.9, 3.68) -> (-1.14, 3.68)
  line L8 (-1.9, 2.48) -> (-1.9, 3.68)
  line L9 (-0.15, 2.48) -> (-0.85, 2.48)
  line L10 (-0.15, 3.68) -> (-0.15, 2.48)
  line L11 (-0.85, 3.68) -> (-0.15, 3.68)
  line L12 (-0.85, 2.48) -> (-0.85, 3.68)
  line L13 (0.85, 2.48) -> (0.15, 2.48)
  line L14 (0.85, 3.68) -> (0.85, 2.48)
  line L15 (0.15, 3.68) -> (0.85, 3.68)
  line L16 (0.15, 2.48) -> (0.15, 3.68)
  line L17 (1.9, 2.48) -> (1.14, 2.48)
  line L18 (1.9, 3.68) -> (1.9, 2.48)
  line L19 (1.14, 3.68) -> (1.9, 3.68)
  line L20 (1.14, 2.48) -> (1.14, 3.68)
  line L21 (3.15, 2.48) -> (2.35, 2.48)
  line L22 (3.15, 3.68) -> (3.15, 2.48)
  line L23 (2.35, 3.68) -> (3.15, 3.68)
  line L24 (2.35, 2.48) -> (2.35, 3.68)
extrude "Extrude5" new body sketch "Board terminations profiles" along normal blind 0.15
work_plane "WorkPlane4" AlongDistance -2 ExtraOffset 0
sketch "Shield stakes profiles" plane through (0, 0, -2) normal (0, 0, 1) x axis (1, 0, 0)
  line L1 (-4.07, 2.5) -> (-4.57, 2.5)
  line L2 (-4.07, 3.5) -> (-4.07, 2.5)
  line L3 (-4.57, 3.5) -> (-4.07, 3.5)
  line L4 (-4.57, 2.5) -> (-4.57, 3.5)
  line L5 (-4.07, -1.3) -> (-4.57, -1.3)
  line L6 (-4.07, -0.3) -> (-4.07, -1.3)
  line L7 (-4.57, -0.3) -> (-4.07, -0.3)
  line L8 (-4.57, -1.3) -> (-4.57, -0.3)
  line L9 (4.57, 2.5) -> (4.07, 2.5)
  line L10 (4.57, 3.5) -> (4.57, 2.5)
  line L11 (4.07, 3.5) -> (4.57, 3.5)
  line L12 (4.07, 2.5) -> (4.07, 3.5)
  line L13 (4.57, -1.3) -> (4.07, -1.3)
  line L14 (4.57, -0.3) -> (4.57, -1.3)
  line L15 (4.07, -0.3) -> (4.57, -0.3)
  line L16 (4.07, -1.3) -> (4.07, -0.3)
extrude "Extrude6" new body sketch "Shield stakes profiles" along normal blind 2.1
work_plane "WorkPlane1" AlongDistance 0.1 ExtraOffset 0
sketch "Component body profile" plane through (0, 0, 0.1) normal (0, 0, 1) x axis (1, 0, 0)
  line L1 (2.25, -1.6) -> (-2.25, -1.6)
  line L2 (2.25, 1.6) -> (2.25, -1.6)
  line L3 (-2.25, 1.6) -> (2.25, 1.6)
  line L4 (-2.25, -1.6) -> (-2.25, 1.6)
extrude "Extrude1" new body sketch "Component body profile" along normal blind 0.6
sketch "Metallized terminations profiles" plane through (0, 0, 0) normal (0, 0, 1) x axis (1, 0, 0)
  line L1 (-1.9, -1.6) -> (-2.3, -1.6)
  line L2 (-1.9, 1.6) -> (-1.9, -1.6)
  line L3 (-2.3, 1.6) -> (-1.9, 1.6)
  line L4 (-2.3, -1.6) -> (-2.3, 1.6)
  line L5 (2.3, -1.6) -> (1.9, -1.6)
  line L6 (2.3, 1.6) -> (2.3, -1.6)
  line L7 (1.9, 1.6) -> (2.3, 1.6)
  line L8 (1.9, -1.6) -> (1.9, 1.6)
extrude "Extrude2" new body sketch "Metallized terminations profiles" along normal blind 0.5
work_plane "WorkPlane1" AlongDistance 0.35 ExtraOffset 0
sketch "Sleeve profile" plane through (0, 0, 0.35) normal (0, 0, 1) x axis (1, 0, 0)
  circle C1 centre (0, 0) radius 3.15
extrude "Extrude1" new body sketch "Sleeve profile" along normal blind 6.65
work_plane "WorkPlane2" AlongDistance 6.92 ExtraOffset 0
sketch "Aluminum vent cap profile" plane through (0, 0, 6.92) normal (0, 0, 1) x axis (1, 0, 0)
  circle C1 centre (0, 0) radius 3
extrude "Extrude2" new body sketch "Aluminum vent cap profile" along normal blind 0.09
work_plane "WorkPlane3" AlongDistance 7.01 ExtraOffset 0
sketch "Pressure vent cross profiles" plane through (0, 0, 7.01) normal (0, 0, 1) x axis (1, 0, 0)
  line L1 (2, -0.07) -> (-2, -0.07)
  line L2 (2, 0.07) -> (2, -0.07)
  line L3 (-2, 0.07) -> (2, 0.07)
  line L4 (-2, -0.07) -> (-2, 0.07)
  line L5 (0.07, -2) -> (-0.07, -2)
  line L6 (0.07, 2) -> (0.07, -2)
  line L7 (-0.07, 2) -> (0.07, 2)
  line L8 (-0.07, -2) -> (-0.07, 2)
extrude "Extrude3" new body sketch "Pressure vent cross profiles" along normal blind 0.015
work_plane "WorkPlane4" AlongDistance -2 ExtraOffset 0
sketch "Radial leads profiles" plane through (0, 0, -2) normal (0, 0, 1) x axis (1, 0, 0)
  line L1 (-1.03, -0.22) -> (-1.47, -0.22)
  line L2 (-1.03, 0.22) -> (-1.03, -0.22)
  line L3 (-1.47, 0.22) -> (-1.03, 0.22)
  line L4 (-1.47, -0.22) -> (-1.47, 0.22)
  line L5 (1.47, -0.22) -> (1.03, -0.22)
  line L6 (1.47, 0.22) -> (1.47, -0.22)
  line L7 (1.03, 0.22) -> (1.47, 0.22)
  line L8 (1.03, -0.22) -> (1.03, 0.22)
extrude "Extrude4" new body sketch "Radial leads profiles" along normal blind 2.7
work_plane "WorkPlane1" AlongDistance 0.1 ExtraOffset 0
sketch "Component body profile" plane through (0, 0, 0.1) normal (0, 0, 1) x axis (1, 0, 0)
  line L1 (1, -0.625) -> (-1, -0.625)
  line L2 (1, 0.625) -> (1, -0.625)
  line L3 (-1, 0.625) -> (1, 0.625)
  line L4 (-1, -0.625) -> (-1, 0.625)
extrude "Extrude1" new body sketch "Component body profile" along normal blind 0.6
sketch "Metallized terminations profiles" plane through (0, 0, 0) normal (0, 0, 1) x axis (1, 0, 0)
  line L1 (-0.65, -0.625) -> (-1.05, -0.625)
  line L2 (-0.65, 0.625) -> (-0.65, -0.625)
  line L3 (-1.05, 0.625) -> (-0.65, 0.625)
  line L4 (-1.05, -0.625) -> (-1.05, 0.625)
  line L5 (1.05, -0.625) -> (0.65, -0.625)
  line L6 (1.05, 0.625) -> (1.05, -0.625)
  line L7 (0.65, 0.625) -> (1.05, 0.625)
  line L8 (0.65, -0.625) -> (0.65, 0.625)
extrude "Extrude2" new body sketch "Metallized terminations profiles" along normal blind 0.5
work_plane "WorkPlane1" AlongDistance 0.1 ExtraOffset 0
sketch "Component body profile" plane through (0, 0, 0.1) normal (0, 0, 1) x axis (1, 0, 0)
  line L1 (1.6, -0.8) -> (-1.6, -0.8)
  line L2 (1.6, 0.8) -> (1.6, -0.8)
  line L3 (-1.6, 0.8) -> (1.6, 0.8)
  line L4 (-1.6, -0.8) -> (-1.6, 0.8)
extrude "Extrude1" new body sketch "Component body profile" along normal blind 0.6
sketch "Metallized terminations profiles" plane through (0, 0, 0) normal (0, 0, 1) x axis (1, 0, 0)
  line L1 (-1.25, -0.8) -> (-1.65, -0.8)
  line L2 (-1.25, 0.8) -> (-1.25, -0.8)
  line L3 (-1.65, 0.8) -> (-1.25, 0.8)
  line L4 (-1.65, -0.8) -> (-1.65, 0.8)
  line L5 (1.65, -0.8) -> (1.25, -0.8)
  line L6 (1.65, 0.8) -> (1.65, -0.8)
  line L7 (1.25, 0.8) -> (1.65, 0.8)
  line L8 (1.25, -0.8) -> (1.25, 0.8)
extrude "Extrude2" new body sketch "Metallized terminations profiles" along normal blind 0.5
work_plane "WorkPlane1" AlongDistance 0.1 ExtraOffset 0
sketch "Component body profile" plane through (0, 0, 0.1) normal (0, 0, 1) x axis (1, 0, 0)
  line L1 (1.6, -0.8) -> (-1.6, -0.8)
  line L2 (1.6, 0.8) -> (1.6, -0.8)
  line L3 (-1.6, 0.8) -> (1.6, 0.8)
  line L4 (-1.6, -0.8) -> (-1.6, 0.8)
extrude "Extrude1" new body sketch "Component body profile" along normal blind 0.6
sketch "Metallized terminations profiles" plane through (0, 0, 0) normal (0, 0, 1) x axis (1, 0, 0)
  line L1 (-1.25, -0.8) -> (-1.65, -0.8)
  line L2 (-1.25, 0.8) -> (-1.25, -0.8)
  line L3 (-1.65, 0.8) -> (-1.25, 0.8)
  line L4 (-1.65, -0.8) -> (-1.65, 0.8)
  line L5 (1.65, -0.8) -> (1.25, -0.8)
  line L6 (1.65, 0.8) -> (1.65, -0.8)
  line L7 (1.25, 0.8) -> (1.65, 0.8)
  line L8 (1.25, -0.8) -> (1.25, 0.8)
extrude "Extrude2" new body sketch "Metallized terminations profiles" along normal blind 0.5
work_plane "WorkPlane1" AlongDistance 0.1 ExtraOffset 0
sketch "Component body profile" plane through (0, 0, 0.1) normal (0, 0, 1) x axis (1, 0, 0)
  line L1 (1, -0.625) -> (-1, -0.625)
  line L2 (1, 0.625) -> (1, -0.625)
  line L3 (-1, 0.625) -> (1, 0.625)
  line L4 (-1, -0.625) -> (-1, 0.625)
extrude "Extrude1" new body sketch "Component body profile" along normal blind 0.6
sketch "Metallized terminations profiles" plane through (0, 0, 0) normal (0, 0, 1) x axis (1, 0, 0)
  line L1 (-0.65, -0.625) -> (-1.05, -0.625)
  line L2 (-0.65, 0.625) -> (-0.65, -0.625)
  line L3 (-1.05, 0.625) -> (-0.65, 0.625)
  line L4 (-1.05, -0.625) -> (-1.05, 0.625)
  line L5 (1.05, -0.625) -> (0.65, -0.625)
  line L6 (1.05, 0.625) -> (1.05, -0.625)
  line L7 (0.65, 0.625) -> (1.05, 0.625)
  line L8 (0.65, -0.625) -> (0.65, 0.625)
extrude "Extrude2" new body sketch "Metallized terminations profiles" along normal blind 0.5
work_plane "WorkPlane1" AlongDistance 0.1 ExtraOffset 0
sketch "Component body profile" plane through (0, 0, 0.1) normal (0, 0, 1) x axis (1, 0, 0)
  line L1 (1, -0.625) -> (-1, -0.625)
  line L2 (1, 0.625) -> (1, -0.625)
  line L3 (-1, 0.625) -> (1, 0.625)
  line L4 (-1, -0.625) -> (-1, 0.625)
extrude "Extrude1" new body sketch "Component body profile" along normal blind 0.6
sketch "Metallized terminations profiles" plane through (0, 0, 0) normal (0, 0, 1) x axis (1, 0, 0)
  line L1 (-0.65, -0.625) -> (-1.05, -0.625)
  line L2 (-0.65, 0.625) -> (-0.65, -0.625)
  line L3 (-1.05, 0.625) -> (-0.65, 0.625)
  line L4 (-1.05, -0.625) -> (-1.05, 0.625)
  line L5 (1.05, -0.625) -> (0.65, -0.625)
  line L6 (1.05, 0.625) -> (1.05, -0.625)
  line L7 (0.65, 0.625) -> (1.05, 0.625)
  line L8 (0.65, -0.625) -> (0.65, 0.625)
extrude "Extrude2" new body sketch "Metallized terminations profiles" along normal blind 0.5
work_plane "WorkPlane1" AlongDistance 0.1 ExtraOffset 0
sketch "Component body profile" plane through (0, 0, 0.1) normal (0, 0, 1) x axis (1, 0, 0)
  line L1 (1, -0.625) -> (-1, -0.625)
  line L2 (1, 0.625) -> (1, -0.625)
  line L3 (-1, 0.625) -> (1, 0.625)
  line L4 (-1, -0.625) -> (-1, 0.625)
extrude "Extrude1" new body sketch "Component body profile" along normal blind 0.6
sketch "Metallized terminations profiles" plane through (0, 0, 0) normal (0, 0, 1) x axis (1, 0, 0)
  line L1 (-0.65, -0.625) -> (-1.05, -0.625)
  line L2 (-0.65, 0.625) -> (-0.65, -0.625)
  line L3 (-1.05, 0.625) -> (-0.65, 0.625)
  line L4 (-1.05, -0.625) -> (-1.05, 0.625)
  line L5 (1.05, -0.625) -> (0.65, -0.625)
  line L6 (1.05, 0.625) -> (1.05, -0.625)
  line L7 (0.65, 0.625) -> (1.05, 0.625)
  line L8 (0.65, -0.625) -> (0.65, 0.625)
extrude "Extrude2" new body sketch "Metallized terminations profiles" along normal blind 0.5
work_plane "WorkPlane1" AlongDistance 0.1 ExtraOffset 0
sketch "Component body profile" plane through (0, 0, 0.1) normal (0, 0, 1) x axis (1, 0, 0)
  line L1 (1, -0.625) -> (-1, -0.625)
  line L2 (1, 0.625) -> (1, -0.625)
  line L3 (-1, 0.625) -> (1, 0.625)
  line L4 (-1, -0.625) -> (-1, 0.625)
extrude "Extrude1" new body sketch "Component body profile" along normal blind 0.6
sketch "Metallized terminations profiles" plane through (0, 0, 0) normal (0, 0, 1) x axis (1, 0, 0)
  line L1 (-0.65, -0.625) -> (-1.05, -0.625)
  line L2 (-0.65, 0.625) -> (-0.65, -0.625)
  line L3 (-1.05, 0.625) -> (-0.65, 0.625)
  line L4 (-1.05, -0.625) -> (-1.05, 0.625)
  line L5 (1.05, -0.625) -> (0.65, -0.625)
  line L6 (1.05, 0.625) -> (1.05, -0.625)
  line L7 (0.65, 0.625) -> (1.05, 0.625)
  line L8 (0.65, -0.625) -> (0.65, 0.625)
extrude "Extrude2" new body sketch "Metallized terminations profiles" along normal blind 0.5
work_plane "WorkPlane1" AlongDistance 0.1 ExtraOffset 0
sketch "Component body profile" plane through (0, 0, 0.1) normal (0, 0, 1) x axis (1, 0, 0)
  line L1 (1, -0.625) -> (-1, -0.625)
  line L2 (1, 0.625) -> (1, -0.625)
  line L3 (-1, 0.625) -> (1, 0.625)
  line L4 (-1, -0.625) -> (-1, 0.625)
extrude "Extrude1" new body sketch "Component body profile" along normal blind 0.6
sketch "Metallized terminations profiles" plane through (0, 0, 0) normal (0, 0, 1) x axis (1, 0, 0)
  line L1 (-0.65, -0.625) -> (-1.05, -0.625)
  line L2 (-0.65, 0.625) -> (-0.65, -0.625)
  line L3 (-1.05, 0.625) -> (-0.65, 0.625)
  line L4 (-1.05, -0.625) -> (-1.05, 0.625)
  line L5 (1.05, -0.625) -> (0.65, -0.625)
  line L6 (1.05, 0.625) -> (1.05, -0.625)
  line L7 (0.65, 0.625) -> (1.05, 0.625)
  line L8 (0.65, -0.625) -> (0.65, 0.625)
extrude "Extrude2" new body sketch "Metallized terminations profiles" along normal blind 0.5
work_plane "WorkPlane1" AlongDistance 0.1 ExtraOffset 0
sketch "Component body profile" plane through (0, 0, 0.1) normal (0, 0, 1) x axis (1, 0, 0)
  line L1 (1, -0.625) -> (-1, -0.625)
  line L2 (1, 0.625) -> (1, -0.625)
  line L3 (-1, 0.625) -> (1, 0.625)
  line L4 (-1, -0.625) -> (-1, 0.625)
extrude "Extrude1" new body sketch "Component body profile" along normal blind 0.6
sketch "Metallized terminations profiles" plane through (0, 0, 0) normal (0, 0, 1) x axis (1, 0, 0)
  line L1 (-0.65, -0.625) -> (-1.05, -0.625)
  line L2 (-0.65, 0.625) -> (-0.65, -0.625)
  line L3 (-1.05, 0.625) -> (-0.65, 0.625)
  line L4 (-1.05, -0.625) -> (-1.05, 0.625)
  line L5 (1.05, -0.625) -> (0.65, -0.625)
  line L6 (1.05, 0.625) -> (1.05, -0.625)
  line L7 (0.65, 0.625) -> (1.05, 0.625)
  line L8 (0.65, -0.625) -> (0.65, 0.625)
extrude "Extrude2" new body sketch "Metallized terminations profiles" along normal blind 0.5
work_plane "WorkPlane1" AlongDistance 0.1 ExtraOffset 0
sketch "Component body profile" plane through (0, 0, 0.1) normal (0, 0, 1) x axis (1, 0, 0)
  line L1 (1, -0.625) -> (-1, -0.625)
  line L2 (1, 0.625) -> (1, -0.625)
  line L3 (-1, 0.625) -> (1, 0.625)
  line L4 (-1, -0.625) -> (-1, 0.625)
extrude "Extrude1" new body sketch "Component body profile" along normal blind 0.6
sketch "Metallized terminations profiles" plane through (0, 0, 0) normal (0, 0, 1) x axis (1, 0, 0)
  line L1 (-0.65, -0.625) -> (-1.05, -0.625)
  line L2 (-0.65, 0.625) -> (-0.65, -0.625)
  line L3 (-1.05, 0.625) -> (-0.65, 0.625)
  line L4 (-1.05, -0.625) -> (-1.05, 0.625)
  line L5 (1.05, -0.625) -> (0.65, -0.625)
  line L6 (1.05, 0.625) -> (1.05, -0.625)
  line L7 (0.65, 0.625) -> (1.05, 0.625)
  line L8 (0.65, -0.625) -> (0.65, 0.625)
extrude "Extrude2" new body sketch "Metallized terminations profiles" along normal blind 0.5
work_plane "WorkPlane1" AlongDistance 0.1 ExtraOffset 0
sketch "Component body profile" plane through (0, 0, 0.1) normal (0, 0, 1) x axis (1, 0, 0)
  line L1 (1, -0.625) -> (-1, -0.625)
  line L2 (1, 0.625) -> (1, -0.625)
  line L3 (-1, 0.625) -> (1, 0.625)
  line L4 (-1, -0.625) -> (-1, 0.625)
extrude "Extrude1" new body sketch "Component body profile" along normal blind 0.6
sketch "Metallized terminations profiles" plane through (0, 0, 0) normal (0, 0, 1) x axis (1, 0, 0)
  line L1 (-0.65, -0.625) -> (-1.05, -0.625)
  line L2 (-0.65, 0.625) -> (-0.65, -0.625)
  line L3 (-1.05, 0.625) -> (-0.65, 0.625)
  line L4 (-1.05, -0.625) -> (-1.05, 0.625)
  line L5 (1.05, -0.625) -> (0.65, -0.625)
  line L6 (1.05, 0.625) -> (1.05, -0.625)
  line L7 (0.65, 0.625) -> (1.05, 0.625)
  line L8 (0.65, -0.625) -> (0.65, 0.625)
extrude "Extrude2" new body sketch "Metallized terminations profiles" along normal blind 0.5
work_plane "WorkPlane1" AlongDistance 0.1 ExtraOffset 0
sketch "Component body profile" plane through (0, 0, 0.1) normal (0, 0, 1) x axis (1, 0, 0)
  line L1 (1, -0.625) -> (-1, -0.625)
  line L2 (1, 0.625) -> (1, -0.625)
  line L3 (-1, 0.625) -> (1, 0.625)
  line L4 (-1, -0.625) -> (-1, 0.625)
extrude "Extrude1" new body sketch "Component body profile" along normal blind 0.6
sketch "Metallized terminations profiles" plane through (0, 0, 0) normal (0, 0, 1) x axis (1, 0, 0)
  line L1 (-0.65, -0.625) -> (-1.05, -0.625)
  line L2 (-0.65, 0.625) -> (-0.65, -0.625)
  line L3 (-1.05, 0.625) -> (-0.65, 0.625)
  line L4 (-1.05, -0.625) -> (-1.05, 0.625)
  line L5 (1.05, -0.625) -> (0.65, -0.625)
  line L6 (1.05, 0.625) -> (1.05, -0.625)
  line L7 (0.65, 0.625) -> (1.05, 0.625)
  line L8 (0.65, -0.625) -> (0.65, 0.625)
extrude "Extrude2" new body sketch "Metallized terminations profiles" along normal blind 0.5
work_plane "WorkPlane1" AlongDistance 0.1 ExtraOffset 0
sketch "Component body profile" plane through (0, 0, 0.1) normal (0, 0, 1) x axis (1, 0, 0)
  line L1 (1, -0.625) -> (-1, -0.625)
  line L2 (1, 0.625) -> (1, -0.625)
  line L3 (-1, 0.625) -> (1, 0.625)
  line L4 (-1, -0.625) -> (-1, 0.625)
extrude "Extrude1" new body sketch "Component body profile" along normal blind 0.6
sketch "Metallized terminations profiles" plane through (0, 0, 0) normal (0, 0, 1) x axis (1, 0, 0)
  line L1 (-0.65, -0.625) -> (-1.05, -0.625)
  line L2 (-0.65, 0.625) -> (-0.65, -0.625)
  line L3 (-1.05, 0.625) -> (-0.65, 0.625)
  line L4 (-1.05, -0.625) -> (-1.05, 0.625)
  line L5 (1.05, -0.625) -> (0.65, -0.625)
  line L6 (1.05, 0.625) -> (1.05, -0.625)
  line L7 (0.65, 0.625) -> (1.05, 0.625)
  line L8 (0.65, -0.625) -> (0.65, 0.625)
extrude "Extrude2" new body sketch "Metallized terminations profiles" along normal blind 0.5
work_plane "WorkPlane1" AlongDistance 0.1 ExtraOffset 0
sketch "Component body profile" plane through (0, 0, 0.1) normal (0, 0, 1) x axis (1, 0, 0)
  line L1 (3, -3) -> (-3, -3)
  line L2 (3, 3) -> (3, -3)
  line L3 (-3, 3) -> (3, 3)
  line L4 (-3, -3) -> (-3, 3)
extrude "Extrude1" new body sketch "Component body profile" along normal blind 2.7
sketch "Metallized terminations profiles" plane through (0, 0, 0) normal (0, 0, 1) x axis (1, 0, 0)
  line L1 (-2.4, -3) -> (-3.05, -3)
  line L2 (-2.4, 3) -> (-2.4, -3)
  line L3 (-3.05, 3) -> (-2.4, 3)
  line L4 (-3.05, -3) -> (-3.05, 3)
  line L5 (3.05, -3) -> (2.4, -3)
  line L6 (3.05, 3) -> (3.05, -3)
  line L7 (2.4, 3) -> (3.05, 3)
  line L8 (2.4, -3) -> (2.4, 3)
extrude "Extrude2" new body sketch "Metallized terminations profiles" along normal blind 0.5
work_plane "WorkPlane2" AlongDistance 2.8 ExtraOffset 0
sketch "4R7 marking" plane through (0, 0, 2.8) normal (0, 0, 1) x axis (1, 0, 0)
  dimension "d1166" = 1.25
  dimension "d1167" = "'4R7'"
extrude "Extrude3" new body sketch "4R7 marking" along normal blind 0.012
work_plane "WorkPlane1" AlongDistance 0.1 ExtraOffset 0
sketch "Component body profile" plane through (0, 0, 0.1) normal (0, 0, 1) x axis (1, 0, 0)
  line L1 (2.25, -1.4) -> (-2.25, -1.4)
  line L2 (2.25, 1.4) -> (2.25, -1.4)
  line L3 (-2.25, 1.4) -> (2.25, 1.4)
  line L4 (-2.25, -1.4) -> (-2.25, 1.4)
extrude "Extrude1" new body sketch "Component body profile" along normal blind 1.9
sketch "Metallized terminations profiles" plane through (0, 0, 0) normal (0, 0, 1) x axis (1, 0, 0)
  line L1 (-1.65, -1.4) -> (-2.3, -1.4)
  line L2 (-1.65, 1.4) -> (-1.65, -1.4)
  line L3 (-2.3, 1.4) -> (-1.65, 1.4)
  line L4 (-2.3, -1.4) -> (-2.3, 1.4)
  line L5 (2.3, -1.4) -> (1.65, -1.4)
  line L6 (2.3, 1.4) -> (2.3, -1.4)
  line L7 (1.65, 1.4) -> (2.3, 1.4)
  line L8 (1.65, -1.4) -> (1.65, 1.4)
extrude "Extrude2" new body sketch "Metallized terminations profiles" along normal blind 0.5
work_plane "WorkPlane2" AlongDistance 2 ExtraOffset 0
sketch "Cathode band profiles" plane through (0, 0, 2) normal (0, 0, 1) x axis (1, 0, 0)
  line L1 (-1.35, -1.4) -> (-1.65, -1.4)
  line L2 (-1.35, 1.4) -> (-1.35, -1.4)
  line L3 (-1.65, 1.4) -> (-1.35, 1.4)
  line L4 (-1.65, -1.4) -> (-1.65, 1.4)
extrude "Extrude3" new body sketch "Cathode band profiles" along normal blind 0.012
